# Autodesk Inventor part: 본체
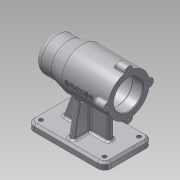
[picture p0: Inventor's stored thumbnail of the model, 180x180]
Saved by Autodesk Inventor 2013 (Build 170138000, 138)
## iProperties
Created: 2019-07
Part Number: 본체
Material: 알루미늄 6061
Document SubType Name: Modeling
Designer: Administrator
Density: 2.71 g/cm^3
Mass: 646.775 g
Surface Area: 654.095 cm^2
Volume: 238.662 cm^3
Author: Administrator
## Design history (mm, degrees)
sketch "스케치1"
  geometry: L1 (-56, 0)-(56, 0); L2 (-56, 0)-(-56, 15); L3 (-46, 25)-(-31, 25); L4 (-31, 25)-(-11, 30); L5 (-11, 30)-(56, 30); L6 (56, 30)-(56, 21); L7 (56, 21)-(41, 21); L8 (41, 21)-(41, 21); L9 (38, 24)-(-10, 24); L10 (-13, 21)-(-13, 21); L11 (-13, 21)-(-24.7, 21); L12 (-25, 20.7)-(-25, 17.5); L13 (-25, 17.5)-(-42.7, 17.5); L14 (-43, 17.2)-(-43, 16); L15 (-43, 16)-(-46.7, 16); L16 (-47, 15.7)-(-47, 10.5); L17 (-50, 7.5)-(-50, 0); L18 (-47, 10.5)-(-47, 10.5); L19 (-50, 0)-(-56, 0); L20 (56, 21)-(56, 0); A1 r 10 centre (-46, 15) between (-46, 25) and (-56, 15); A2 r 3 centre (-47, 7.5) between (-47, 10.5) and (-50, 7.5); A3 r 0.3 centre (-46.7, 15.7) between (-46.7, 16) and (-47, 15.7); A4 r 0.3 centre (-42.7, 17.2) between (-42.7, 17.5) and (-43, 17.2); A5 r 0.3 centre (-24.7, 20.7) between (-24.7, 21) and (-25, 20.7); A6 r 3 centre (-10, 21) between (-10, 24) and (-13, 21); A7 r 3 centre (38, 21) between (41, 21) and (38, 24); 5 further points
  constraints: 40 end point, 14 point on circle, 14 tangent, 9 parallel, 7 centre point, 7 perpendicular, 7 point on line, 4 equal radius, 2 collinear, 2 horizontal, 1 coincident, 1 midpoint
  dimensions: "d0" = 112 distance of L1.start L1.end; "d2" = 45 distance from line of L4.end L2; "d3" = 25 distance of L3.end point (-56, 25); "d4" = 60 diameter of L5 L1; "d5" = 50 diameter of L3 L1; "d6" = 15 distance of L6.end L7.end; "d7" = 42 diameter of L7 L1; "d8" = 54 distance of point (41, 24) point (-13, 24); "d9" = 48 diameter of L9 L1; "d10" = 42 diameter of L11 L1; "d11" = 12 distance between parallel lines of L12 L10; "d12" = 18 distance between parallel lines of L14 L12; "d13" = 35 diameter of L13 L1; "d14" = 32 diameter of L15 L1; "d15" = 4 distance between parallel lines of L16 L14; "d16" = 3 distance between parallel lines of L17 L16; "d17" = 21 diameter of L16.end L1; "d18" = 10 radius of A1; "d19" = 3 radius of A2; "d20" = 0.3 radius of A3
revolve "회전1" sketch "스케치1" stored, may be unused: angle "d21" = 90 deg
sketch "스케치2"
  geometry: C1 r 21 at (0, 0) reference; A1 r 30 centre (0, 0) between (5.97, 29.4) and (-5.97, 29.4) reference; A2 r 6 centre (0, 30) between (5.97, 29.4) and (-5.97, 29.4); A3 r 30 centre (0, 0) between (5.97, 29.4) and (-5.97, 29.4)
  constraints: 7 point on circle, 2 centre point, 1 vertical alignment
  dimensions: "d22" = 30 distance of C1.centre A2.centre; "d23" = 12 diameter of A2
extrude "돌출1" join sketch "스케치2" distance "d24" = 16; taper "d25" = 0 deg
sketch "스케치3"
  geometry: A1 r 6 centre (-30, -30) between (-29.4, -24.03) and (-29.4, -35.97) reference; A2 r 6 centre (0, -60) between (-5.97, -59.4) and (5.97, -59.4) reference; A3 r 6 centre (30, -30) between (29.4, -35.97) and (29.4, -24.03) reference; A4 r 6 centre (0, 0) between (5.97, -0.6) and (-5.97, -0.6) reference; 4 further points
  constraints: 4 coincident
hole "구멍1" sketch "스케치3" at (0, 0), (-30, -30), (0, -60), (30, -30) diameter "d29" = 3.242; stored, may be unused: countersink angle "d33" = 90 deg, drill point angle "d35" = 118 deg; dims "d30" = 8, "d31" = 4, "d32" = 2, "d34" = 11
sketch "스케치4"
  geometry: L1 (-56, -80)-(56, -80); L2 (56, -80)-(56, -70); L3 (56, -70)-(-56, -70); L4 (-56, -70)-(-56, -80); 2 further points
  constraints: 8 end point, 2 parallel, 1 horizontal, 1 midpoint, 1 perpendicular, 1 vertical alignment
  dimensions: "d36" = 10 distance of L1.end L2.end; "d38" = 80 distance from line of point (0, 0) L1; "d39" = 112 distance of L1.start L1.end
extrude "돌출2" join sketch "스케치4" stored distance "d40" = 70; taper "d41" = 0 deg
sketch "스케치5"
  geometry: L1 (0, 70)-(0, 0) reference; L2 (112, 70)-(112, 0) reference; L3 (0, 70)-(112, 70) reference; L4 (52, 7)-(60, 7); L5 (60, 7)-(60, 63); L6 (60, 63)-(52, 63); L7 (52, 63)-(52, 7); L8 (52, 7)-(60, 63); L9 (60, 7)-(52, 63); L10 (20, 31)-(87, 31); L11 (87, 31)-(87, 39); L12 (87, 39)-(20, 39); L13 (20, 39)-(20, 31); 3 further points
  constraints: 20 end point, 4 midpoint, 4 parallel, 2 horizontal, 2 perpendicular, 1 horizontal alignment
  dimensions: "d42" = 8 distance of L5.end L6.end; "d46" = 7 distance between parallel lines of L3 L6; "d47" = 8 distance of L12.end L10.start; "d48" = 20 distance between parallel lines of L1 L13; "d49" = 25 distance between parallel lines of L2 L11
extrude "돌출3" join sketch "스케치5" stored distance "d50" = 70; taper "d51" = 0 deg
feature "면 기울기1" dims angle "d52" = 20 deg
feature "면 기울기2" dims angle "d53" = 10 deg
feature "면 기울기3" dims angle "d54" = 10 deg
fillet "모깎기1" dims "d55" = 10
sketch "스케치6"
  geometry: A1 r 10 centre (0, 60) between (0, 70) and (-10, 60) reference; A2 r 10 centre (0, 10) between (-10, 10) and (0, 0) reference; A3 r 10 centre (92, 10) between (92, 0) and (102, 10) reference; A4 r 10 centre (92, 60) between (102, 60) and (92, 70) reference; 5 further points
  constraints: 4 coincident
hole "구멍2" sketch "스케치6" at (0, 60), (92, 60), (92, 10), (0, 10) diameter "d56" = 6; stored, may be unused: countersink angle "d60" = 90 deg, drill point angle "d62" = 118 deg; dims "d57" = 8, "d58" = 4, "d59" = 2, "d61" = 11
node "작업 평면2"
sketch "스케치7"
  geometry: L1 (33.5, 5.97)-(33.5, 29.4) reference; 2 further points
  constraints: 1 horizontal alignment, 1 other
  dimensions: "d63" = 42 distance from line of L1 point (-8.5, 0)
feature "엠보싱1" sketch "스케치7" dims "d0" = 112, "d2" = 45, "d3" = 25, "d4" = 60, "d5" = 50, "d6" = 15, "d7" = 42, "d8" = 54, "d9" = 48, "d10" = 42, "d11" = 12, "d12" = 18, "d13" = 35, "d14" = 32, "d15" = 4, "d16" = 3, "d17" = 21, "d18" = 10, "d19" = 3, "d20" = 0.3, "d64" = 0.5, "d65" = 0
fillet "모깎기2" dims "d66" = 3
fillet "모깎기3" dims "d67" = 1
fillet "모깎기4" dims "d68" = 3
fillet "모깎기5" dims "d69" = 3
fillet "모깎기6" dims "d70" = 3
chamfer "모따기1" distance "d71" = 1; stored, may be unused: second distance "d72" = 2, angle "d73" = 45 deg
chamfer "모따기2" distance "d74" = 3; stored, may be unused: second distance "d75" = 2, angle "d76" = 45 deg
node "솔리드1"
pattern_circular "원형 패턴1" dims angle "d27" = 360 deg
